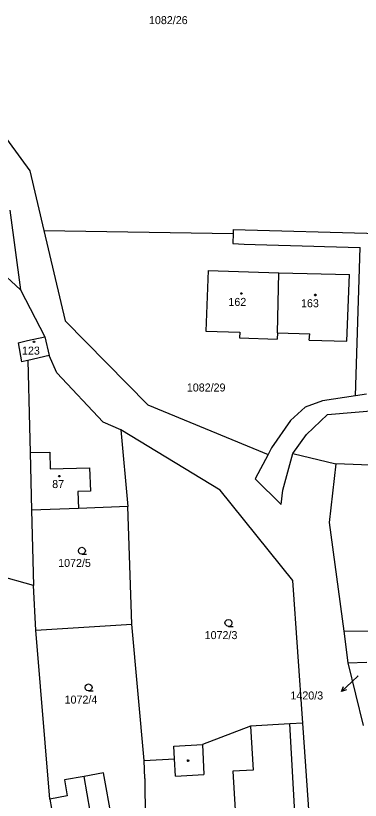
# Model space of a CAD drawing. Extents: x -852001 to -842497, y -1063614 to -1052182.
# Drawn here: x -849639.2 to -849566, y -1056338.8 to -1056172.2 of the extents above; entities that cross this region are included whole.
import ezdxf

# ---------------------------------------------------------------- set-up
doc = ezdxf.new("R2010")
doc.units = 0
for name, color, linetype in [('Default', 7, 'Continuous'), ('KN_HRANICE', 7, 'Continuous'), ('KN_KULTURY', 7, 'Continuous'), ('KN_PARCELY', 7, 'Continuous'), ('KN_SLUCKY', 7, 'Continuous')]:
    doc.layers.add(name, color=color, linetype=linetype)

# ---------------------------------------------------------------- blocks, each defined once
blk = doc.blocks.new('304')
at = {"layer": 'Default'}
blk.add_lwpolyline([(0, 0), (-0.38, 0.1), (-0.65, 0.37), (-0.75, 0.74), (-0.65, 1.11), (-0.38, 1.38), (-0.01, 1.48), (0.36, 1.38), (0.63, 1.11), (0.73, 0.73), (0.63, 0.35), (0.36, 0.08), (-0.02, -0.02), (0.98, -0.02)], dxfattribs=at)
blk = doc.blocks.new('10292')
at = {"layer": 'Default'}
blk.add_line((0, 3), (0, 0), dxfattribs=at)
blk.add_lwpolyline([(-0.5, 2), (0, 3), (0.5, 2)], dxfattribs=at)
blk = doc.blocks.new('402')
at = {"layer": 'Default'}
blk.add_lwpolyline([(0.09, 0.15), (0.18, 0), (0.09, -0.15), (-0.09, -0.15), (-0.18, 0), (-0.09, 0.15), (0.09, 0.15)], dxfattribs=at)

msp = doc.modelspace()

# ---------------------------------------------------------------- linework, layer by layer
at = {"layer": 'KN_HRANICE'}
for p, q in [((-849647.93, -1056189.13), (-849636.21, -1056205.16)), ((-849636.21, -1056205.16), (-849633.22, -1056217.81)), ((-849659.31, -1056210.99), (-849638.15, -1056230.4)), ((-849640.45, -1056213.48), (-849638.15, -1056230.4)), ((-849633.22, -1056217.81), (-849628.68, -1056237)), ((-849633.22, -1056217.81), (-849593, -1056218.48)), ((-849593, -1056218.48), (-849593.09, -1056220.61)), ((-849592.97, -1056217.6), (-849593, -1056218.48)), ((-849592.97, -1056217.6), (-849552.87, -1056218.73)), ((-849593.09, -1056220.61), (-849590.62, -1056220.75)), ((-849590.62, -1056220.75), (-849588.34, -1056220.78)), ((-849588.34, -1056220.78), (-849575.82, -1056221.16)), ((-849575.82, -1056221.16), (-849573.55, -1056221.23)), ((-849573.55, -1056221.23), (-849566.03, -1056221.45)), ((-849567, -1056252.9), (-849566.03, -1056221.45)), ((-849598.32, -1056226.32), (-849598.78, -1056239.21)), ((-849598.32, -1056226.32), (-849583.29, -1056226.79)), ((-849583.59, -1056239.57), (-849583.29, -1056226.79)), ((-849583.29, -1056226.79), (-849568.24, -1056227.17)), ((-849568.82, -1056241.34), (-849568.24, -1056227.17)), ((-849638.15, -1056230.4), (-849633.01, -1056240.36)), ((-849628.68, -1056237), (-849611.09, -1056254.85)), ((-849598.78, -1056239.21), (-849591.59, -1056239.38)), ((-849591.59, -1056239.38), (-849591.62, -1056240.61)), ((-849583.59, -1056239.57), (-849583.62, -1056240.86)), ((-849583.59, -1056239.57), (-849576.72, -1056239.73)), ((-849576.82, -1056241.08), (-849576.72, -1056239.73)), ((-849638.66, -1056241.65), (-849636.68, -1056241.2)), ((-849638.66, -1056241.65), (-849637.96, -1056245.71)), ((-849636.68, -1056241.2), (-849633.01, -1056240.36)), ((-849633.01, -1056240.36), (-849632.08, -1056244.36)), ((-849591.62, -1056240.61), (-849583.62, -1056240.86)), ((-849576.82, -1056241.08), (-849568.82, -1056241.34)), ((-849632.08, -1056244.36), (-849636.59, -1056245.4)), ((-849630.46, -1056248.02), (-849632.08, -1056244.36)), ((-849636.59, -1056245.4), (-849637.96, -1056245.71)), ((-849636.59, -1056245.4), (-849636.24, -1056259.43)), ((-849620.64, -1056258.54), (-849630.46, -1056248.02)), ((-849567, -1056252.9), (-849574.02, -1056253.95)), ((-849572.97, -1056256.89), (-849521.28, -1056252.42)), ((-849564.68, -1056252.6), (-849567, -1056252.9)), ((-849611.09, -1056254.85), (-849585.58, -1056265.38)), ((-849574.02, -1056253.95), (-849577.71, -1056255.35)), ((-849577.71, -1056255.35), (-849580.82, -1056258.14)), ((-849577.42, -1056261.13), (-849572.97, -1056256.89)), ((-849616.86, -1056260.15), (-849620.64, -1056258.54)), ((-849580.82, -1056258.14), (-849584.82, -1056263.95)), ((-849636.24, -1056259.43), (-849636.1, -1056264.92)), ((-849595.77, -1056272.93), (-849616.86, -1056260.15)), ((-849616.86, -1056260.15), (-849615.36, -1056276.4)), ((-849580.29, -1056265.17), (-849577.42, -1056261.13)), ((-849636.1, -1056264.92), (-849635.8, -1056277.2)), ((-849584.82, -1056263.95), (-849585.58, -1056265.38)), ((-849582.46, -1056272.94), (-849580.29, -1056265.17)), ((-849580.29, -1056265.17), (-849571.14, -1056267.35)), ((-849585.58, -1056265.38), (-849588.32, -1056270.53)), ((-849571.14, -1056267.35), (-849572.59, -1056279.79)), ((-849543.36, -1056268.51), (-849571.14, -1056267.35)), ((-849588.32, -1056270.53), (-849582.79, -1056275.99)), ((-849580.33, -1056292.14), (-849595.77, -1056272.93)), ((-849582.79, -1056275.99), (-849582.46, -1056272.94)), ((-849625.82, -1056276.81), (-849635.8, -1056277.2)), ((-849615.36, -1056276.4), (-849625.82, -1056276.81)), ((-849614.51, -1056301.38), (-849615.36, -1056276.4)), ((-849635.8, -1056277.2), (-849635.4, -1056293.21)), ((-849572.59, -1056279.79), (-849569.5, -1056302.91)), ((-849635.4, -1056293.21), (-849664.73, -1056284.95)), ((-849634.92, -1056302.69), (-849635.4, -1056293.21)), ((-849578.15, -1056322.42), (-849580.33, -1056292.14)), ((-849634.92, -1056302.69), (-849614.51, -1056301.38)), ((-849611.88, -1056330.31), (-849614.51, -1056301.38)), ((-849631.91, -1056338.54), (-849634.92, -1056302.69)), ((-849569.5, -1056302.91), (-849541.91, -1056302.5)), ((-849569.5, -1056302.91), (-849568.61, -1056309.6)), ((-849568.61, -1056309.6), (-849564.57, -1056309.49)), ((-849568.61, -1056309.6), (-849565.38, -1056322.92)), ((-849589.28, -1056323.07), (-849599.48, -1056326.92)), ((-849580.93, -1056322.58), (-849589.28, -1056323.07)), ((-849578.15, -1056322.42), (-849580.93, -1056322.58)), ((-849576.45, -1056347.39), (-849578.15, -1056322.42)), ((-849605.58, -1056327.27), (-849599.48, -1056326.92)), ((-849605.43, -1056329.98), (-849605.58, -1056327.27)), ((-849611.88, -1056330.31), (-849605.43, -1056329.98)), ((-849611.73, -1056334.13), (-849611.88, -1056330.31)), ((-849620.5, -1056332.96), (-849624.66, -1056333.71)), ((-849616.72, -1056354), (-849620.5, -1056332.96)), ((-849624.66, -1056333.71), (-849628.83, -1056334.46)), ((-849628.83, -1056334.46), (-849628.22, -1056337.88)), ((-849611.73, -1056334.13), (-849611.68, -1056353.09)), ((-849628.22, -1056337.88), (-849631.91, -1056338.54)), ((-849631.91, -1056338.54), (-849631.2, -1056342.49))]:
    msp.add_line(p, q, dxfattribs=at)
at = {"layer": 'KN_PARCELY'}
msp.add_line((-849566.46, -1056312.38), (-849567.77, -1056313.63), dxfattribs=at)
at = {"layer": 'KN_SLUCKY'}
for p, q in [((-849636.1, -1056264.92), (-849631.95, -1056264.87)), ((-849631.95, -1056264.87), (-849631.85, -1056268.44)), ((-849631.85, -1056268.44), (-849623.51, -1056268.22)), ((-849623.51, -1056268.22), (-849623.32, -1056273.14)), ((-849623.32, -1056273.14), (-849625.96, -1056273.24)), ((-849625.96, -1056273.24), (-849625.82, -1056276.81)), ((-849589.28, -1056323.07), (-849588.73, -1056332.37)), ((-849579.67, -1056345.88), (-849580.93, -1056322.58)), ((-849599.48, -1056326.92), (-849599.25, -1056333.3)), ((-849605.22, -1056333.64), (-849605.43, -1056329.98)), ((-849605.22, -1056333.64), (-849599.25, -1056333.3)), ((-849588.73, -1056332.37), (-849593.06, -1056332.62)), ((-849593.06, -1056332.62), (-849592.57, -1056340.88)), ((-849623.34, -1056341.09), (-849624.66, -1056333.71))]:
    msp.add_line(p, q, dxfattribs=at)

# ---------------------------------------------------------------- block references
at = {"layer": 'KN_KULTURY'}
for name, p in [('402', (-849591.23, -1056231.17)), ('402', (-849575.51, -1056231.51)), ('402', (-849635.3, -1056241.47)), ('402', (-849629.91, -1056269.99)), ('304', (-849625.11, -1056286.55)), ('304', (-849593.98, -1056301.87)), ('304', (-849623.7, -1056315.56)), ('402', (-849602.56, -1056330.38))]:
    msp.add_blockref(name, p, dxfattribs=at)
at = {"layer": 'KN_PARCELY', "rotation": 133.499166}
msp.add_blockref('10292', (-849567.77, -1056313.63), dxfattribs=at)

# ---------------------------------------------------------------- texts
at = {"layer": 'KN_PARCELY'}
for s, p in [('1082/26', (-849610.87, -1056174)), ('162', (-849594, -1056233.83)), ('163', (-849578.57, -1056234.11)), ('123', (-849637.85, -1056244.17)), ('1082/29', (-849602.83, -1056252)), ('87', (-849631.43, -1056272.5)), ('1072/5', (-849630.17, -1056289.25)), ('1072/3', (-849599.04, -1056304.57)), ('1072/4', (-849628.8, -1056318.26)), ('1420/3', (-849580.82, -1056317.39))]:
    msp.add_text(s, height=1.7, dxfattribs=at).set_placement(p)
msp.add_text('1420/3', height=0.1, rotation=90.642, dxfattribs=at).set_placement((-849566.46, -1056312.63))

doc.saveas('drawing.dxf')
